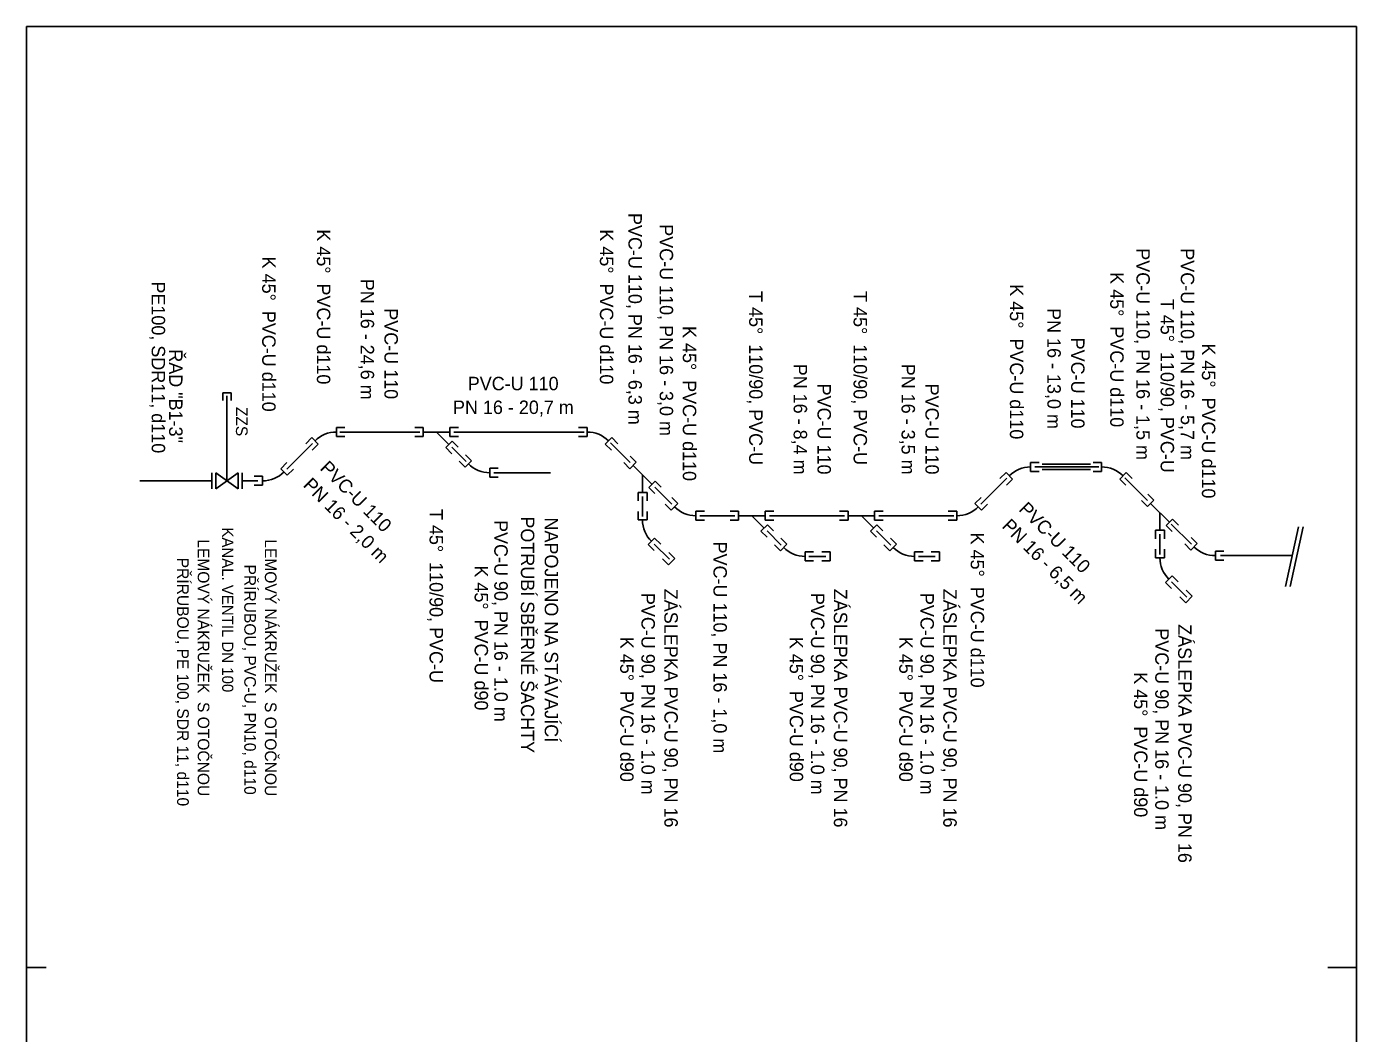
# Model space of a CAD drawing. Extents: x -549136 to -548786, y -1151900 to -1151213.
# Drawn here: x -549136 to -548987.5, y -1151446.3 to -1151333.9 of the extents above; entities that cross this region are included whole.
import ezdxf

# ---------------------------------------------------------------- set-up
doc = ezdxf.new("R2010")
doc.units = 0
doc.layers.add('Vrstva 2', color=7, linetype='Continuous')

msp = doc.modelspace()

# ---------------------------------------------------------------- linework, layer by layer
at = {"layer": 'Vrstva 2'}
for p, q in [((-548987.55, -1151333.9), (-549136.05, -1151333.9)), ((-549136.05, -1151333.9), (-549136.05, -1151438.9)), ((-548987.55, -1151438.9), (-548987.55, -1151333.9)), ((-549114.14, -1151374.78), (-549113.19, -1151374.78)), ((-549114.14, -1151374.78), (-549114.14, -1151375.64)), ((-549113.67, -1151384.6), (-549113.67, -1151375.12)), ((-549113.19, -1151374.78), (-549113.19, -1151375.64)), ((-549104.19, -1151379.78), (-549104.87, -1151380.46)), ((-549104.19, -1151379.78), (-549103.48, -1151380.5)), ((-549101.45, -1151379.66), (-549101.45, -1151378.65)), ((-549101.45, -1151378.65), (-549100.5, -1151378.65)), ((-549101.45, -1151379.66), (-549100.5, -1151379.66)), ((-549101.06, -1151379.15), (-549092.14, -1151379.15)), ((-549091.75, -1151378.65), (-549092.7, -1151378.65)), ((-549091.75, -1151379.66), (-549092.7, -1151379.66)), ((-549091.75, -1151378.65), (-549091.75, -1151379.66)), ((-549091.75, -1151379.15), (-549088.78, -1151379.15)), ((-549090.26, -1151379.15), (-549088.88, -1151380.53)), ((-549088.78, -1151378.65), (-549088.78, -1151379.66)), ((-549088.78, -1151378.65), (-549087.83, -1151378.65)), ((-549088.78, -1151379.66), (-549087.83, -1151379.66)), ((-549088.33, -1151379.15), (-549073.77, -1151379.15)), ((-549073.45, -1151378.65), (-549074.4, -1151378.65)), ((-549073.45, -1151379.66), (-549074.4, -1151379.66)), ((-549073.45, -1151378.65), (-549073.45, -1151379.66)), ((-549071.42, -1151380.5), (-549070.7, -1151379.78)), ((-549070.7, -1151379.78), (-549070.03, -1151380.46)), ((-549107, -1151383.31), (-549104.12, -1151380.43)), ((-549103.48, -1151380.5), (-549104.15, -1151381.18)), ((-549088.52, -1151380.17), (-549089.24, -1151380.89)), ((-549089.24, -1151380.89), (-549088.57, -1151381.57)), ((-549088.57, -1151380.85), (-549086.97, -1151382.45)), ((-549088.52, -1151380.17), (-549087.85, -1151380.85)), ((-549071.42, -1151380.5), (-549070.74, -1151381.18)), ((-549070.85, -1151380.35), (-549068.65, -1151382.55)), ((-549107.66, -1151383.25), (-549106.98, -1151382.57)), ((-549087.07, -1151383.07), (-549087.74, -1151382.39)), ((-549086.35, -1151382.35), (-549087.07, -1151383.07)), ((-549086.35, -1151382.35), (-549087.02, -1151381.68)), ((-549068.68, -1151383.25), (-549069.35, -1151382.57)), ((-549067.96, -1151382.53), (-549068.68, -1151383.25)), ((-549067.96, -1151382.53), (-549068.63, -1151381.85)), ((-549023.93, -1151383.56), (-549023.93, -1151382.54)), ((-549023.93, -1151382.54), (-549022.97, -1151382.54)), ((-549022.65, -1151382.75), (-549017.24, -1151382.75)), ((-549016, -1151382.54), (-549016.95, -1151382.54)), ((-549016, -1151382.54), (-549016, -1151383.56)), ((-549115.35, -1151385.5), (-549115.35, -1151383.7)), ((-549114.92, -1151385.5), (-549114.92, -1151383.7)), ((-549114.92, -1151383.7), (-549112.42, -1151385.5)), ((-549112.42, -1151383.7), (-549114.92, -1151385.5)), ((-549112.42, -1151385.5), (-549112.42, -1151383.7)), ((-549111.98, -1151385.5), (-549111.98, -1151383.7)), ((-549109.69, -1151384.09), (-549110.64, -1151384.09)), ((-549109.69, -1151384.09), (-549109.69, -1151385.1)), ((-549106.94, -1151383.97), (-549107.66, -1151383.25)), ((-549106.94, -1151383.97), (-549106.26, -1151383.29)), ((-549084.32, -1151384.2), (-549084.32, -1151383.19)), ((-549084.32, -1151383.19), (-549083.37, -1151383.19)), ((-549084.32, -1151384.2), (-549083.37, -1151384.2)), ((-549083.88, -1151383.7), (-549077.56, -1151383.7)), ((-549068.32, -1151382.89), (-549066.22, -1151384.98)), ((-549067.27, -1151383.94), (-549067.27, -1151385.89)), ((-549029.48, -1151387.21), (-549026.6, -1151384.32)), ((-549026.67, -1151383.68), (-549027.35, -1151384.35)), ((-549026.67, -1151383.68), (-549025.95, -1151384.4)), ((-549023.93, -1151383.56), (-549022.97, -1151383.56)), ((-549023.47, -1151383.05), (-549016.32, -1151383.05)), ((-549022.65, -1151383.35), (-549017.24, -1151383.35)), ((-549016, -1151383.56), (-549016.95, -1151383.56)), ((-549013.97, -1151384.4), (-549013.25, -1151383.68)), ((-549013.4, -1151384.25), (-549010.87, -1151386.78)), ((-549013.25, -1151383.68), (-549012.58, -1151384.35)), ((-549117.11, -1151384.6), (-549123.41, -1151384.6)), ((-549115.35, -1151384.6), (-549117.11, -1151384.6)), ((-549110.22, -1151384.6), (-549111.98, -1151384.6)), ((-549109.69, -1151385.1), (-549110.64, -1151385.1)), ((-549065.86, -1151384.63), (-549066.58, -1151385.34)), ((-549066.58, -1151385.34), (-549065.9, -1151386.02)), ((-549065.9, -1151385.31), (-549063.99, -1151387.21)), ((-549065.86, -1151384.63), (-549065.18, -1151385.3)), ((-549025.95, -1151384.4), (-549026.63, -1151385.07)), ((-549013.97, -1151384.4), (-549013.3, -1151385.07)), ((-549066.76, -1151385.89), (-549067.77, -1151385.89)), ((-549067.77, -1151385.89), (-549067.77, -1151386.84)), ((-549067.27, -1151386.33), (-549067.27, -1151388.59)), ((-549066.76, -1151385.89), (-549066.76, -1151386.84)), ((-549064.06, -1151387.86), (-549064.73, -1151387.19)), ((-549063.34, -1151387.14), (-549064.06, -1151387.86)), ((-549063.34, -1151387.14), (-549064.01, -1151386.47)), ((-549030.14, -1151387.14), (-549029.46, -1151386.47)), ((-549029.42, -1151387.86), (-549030.14, -1151387.14)), ((-549029.42, -1151387.86), (-549028.74, -1151387.19)), ((-549010.89, -1151387.48), (-549011.56, -1151386.8)), ((-549010.17, -1151386.76), (-549010.89, -1151387.48)), ((-549010.17, -1151386.76), (-549010.84, -1151386.08)), ((-549010.53, -1151387.12), (-549008.43, -1151389.22)), ((-549067.77, -1151388.96), (-549067.77, -1151388.01)), ((-549066.76, -1151388.96), (-549066.76, -1151388.01)), ((-549061.31, -1151389), (-549061.31, -1151387.98)), ((-549061.31, -1151387.98), (-549060.36, -1151387.98)), ((-549060.87, -1151388.49), (-549056.94, -1151388.49)), ((-549056.54, -1151387.98), (-549057.49, -1151387.98)), ((-549056.54, -1151387.98), (-549056.54, -1151389)), ((-549056.54, -1151388.49), (-549053.57, -1151388.49)), ((-549055.06, -1151388.49), (-549053.68, -1151389.87)), ((-549053.57, -1151387.98), (-549053.57, -1151389)), ((-549053.57, -1151387.98), (-549052.62, -1151387.98)), ((-549053.1, -1151388.49), (-549044.71, -1151388.49)), ((-549044.31, -1151387.98), (-549045.27, -1151387.98)), ((-549044.31, -1151387.98), (-549044.31, -1151389)), ((-549044.31, -1151388.49), (-549041.35, -1151388.49)), ((-549042.83, -1151388.49), (-549041.45, -1151389.87)), ((-549041.35, -1151387.98), (-549041.35, -1151389)), ((-549041.35, -1151387.98), (-549040.4, -1151387.98)), ((-549040.88, -1151388.49), (-549032.49, -1151388.49)), ((-549032.16, -1151387.98), (-549033.12, -1151387.98)), ((-549032.16, -1151387.98), (-549032.16, -1151389)), ((-549009.48, -1151388.17), (-549009.48, -1151390.12)), ((-549066.76, -1151388.96), (-549067.77, -1151388.96)), ((-549061.31, -1151389), (-549060.36, -1151389)), ((-549056.54, -1151389), (-549057.49, -1151389)), ((-549053.32, -1151389.51), (-549054.04, -1151390.23)), ((-549054.04, -1151390.23), (-549053.36, -1151390.9)), ((-549053.57, -1151389), (-549052.62, -1151389)), ((-549053.36, -1151390.18), (-549051.77, -1151391.78)), ((-549053.32, -1151389.51), (-549052.65, -1151390.18)), ((-549044.31, -1151389), (-549045.27, -1151389)), ((-549041.09, -1151389.51), (-549041.81, -1151390.23)), ((-549041.81, -1151390.23), (-549041.14, -1151390.9)), ((-549041.35, -1151389), (-549040.4, -1151389)), ((-549041.14, -1151390.18), (-549039.54, -1151391.78)), ((-549041.09, -1151389.51), (-549040.42, -1151390.18)), ((-549032.16, -1151389), (-549033.12, -1151389)), ((-549008.97, -1151390.12), (-549009.99, -1151390.12)), ((-549009.99, -1151390.12), (-549009.99, -1151391.07)), ((-549008.97, -1151390.12), (-549008.97, -1151391.07)), ((-549008.07, -1151388.86), (-549008.79, -1151389.58)), ((-549008.79, -1151389.58), (-549008.12, -1151390.25)), ((-549008.22, -1151389.43), (-549005.98, -1151391.66)), ((-549008.07, -1151388.86), (-549007.4, -1151389.53)), ((-548994, -1151389.73), (-548995.46, -1151396.4)), ((-548993.48, -1151389.73), (-548994.94, -1151396.4)), ((-549066.64, -1151391.71), (-549065.92, -1151390.99)), ((-549066.64, -1151391.71), (-549065.96, -1151392.38)), ((-549065.97, -1151391.66), (-549064.27, -1151393.35)), ((-549065.92, -1151390.99), (-549065.24, -1151391.66)), ((-549051.86, -1151392.4), (-549052.54, -1151391.73)), ((-549051.14, -1151391.68), (-549051.86, -1151392.4)), ((-549051.14, -1151391.68), (-549051.82, -1151391.01)), ((-549039.64, -1151392.4), (-549040.31, -1151391.73)), ((-549038.92, -1151391.68), (-549039.64, -1151392.4)), ((-549038.92, -1151391.68), (-549039.59, -1151391.01)), ((-549009.48, -1151390.56), (-549009.48, -1151392.82)), ((-549006.05, -1151392.32), (-549006.72, -1151391.64)), ((-549005.33, -1151391.6), (-549006.05, -1151392.32)), ((-549005.33, -1151391.6), (-549006, -1151390.93)), ((-549064.38, -1151393.97), (-549063.66, -1151393.25)), ((-549063.66, -1151393.25), (-549064.33, -1151392.58)), ((-549049.11, -1151393.54), (-549049.11, -1151392.52)), ((-549049.11, -1151392.52), (-549048.16, -1151392.52)), ((-549048.68, -1151393.03), (-549046.81, -1151393.03)), ((-549046.31, -1151392.52), (-549047.26, -1151392.52)), ((-549046.31, -1151392.52), (-549046.31, -1151393.54)), ((-549036.89, -1151393.54), (-549036.89, -1151392.52)), ((-549036.89, -1151392.52), (-549035.94, -1151392.52)), ((-549036.45, -1151393.03), (-549034.58, -1151393.03)), ((-549034.09, -1151392.52), (-549035.04, -1151392.52)), ((-549034.09, -1151392.52), (-549034.09, -1151393.54)), ((-549009.99, -1151393.19), (-549009.99, -1151392.24)), ((-549008.97, -1151393.19), (-549009.99, -1151393.19)), ((-549008.97, -1151393.19), (-549008.97, -1151392.24)), ((-549003.3, -1151393.46), (-549003.3, -1151392.44)), ((-549003.3, -1151392.44), (-549002.35, -1151392.44)), ((-549002.73, -1151392.95), (-548994.7, -1151392.95)), ((-549064.38, -1151393.97), (-549065.05, -1151393.3)), ((-549049.11, -1151393.54), (-549048.16, -1151393.54)), ((-549046.31, -1151393.54), (-549047.26, -1151393.54)), ((-549036.89, -1151393.54), (-549035.94, -1151393.54)), ((-549034.09, -1151393.54), (-549035.04, -1151393.54)), ((-549003.3, -1151393.46), (-549002.35, -1151393.46)), ((-549008.85, -1151395.94), (-549008.13, -1151395.22)), ((-549008.85, -1151395.94), (-549008.18, -1151396.61)), ((-549008.18, -1151395.89), (-549006.49, -1151397.58)), ((-549008.13, -1151395.22), (-549007.46, -1151395.89)), ((-549006.59, -1151398.2), (-549007.26, -1151397.53)), ((-549006.59, -1151398.2), (-549005.87, -1151397.48)), ((-549005.87, -1151397.48), (-549006.54, -1151396.81)), ((-549136.05, -1151438.9), (-549136.05, -1151543.9)), ((-549133.86, -1151438.9), (-549136.05, -1151438.9)), ((-548987.55, -1151438.9), (-548990.75, -1151438.9)), ((-548987.55, -1151543.9), (-548987.55, -1151438.9))]:
    msp.add_line(p, q, dxfattribs=at)
for centre, start, end in [((-549101.45, -1151382.53), 90, 135), ((-549073.45, -1151382.53), 45, 90), ((-549084.32, -1151380.32), 225, 270), ((-549109.69, -1151381.22), 270, 315), ((-549023.93, -1151386.43), 90, 135), ((-549016, -1151386.43), 45, 90), ((-549061.31, -1151385.11), 225, 270), ((-549032.16, -1151385.11), 270, 315), ((-549063.89, -1151388.96), 180, 225), ((-549049.11, -1151389.65), 225, 270), ((-549036.89, -1151389.65), 225, 270), ((-549006.1, -1151393.19), 180, 225), ((-549003.3, -1151389.57), 225, 270)]:
    msp.add_arc(centre, 3.38, start, end, dxfattribs=at)

# ---------------------------------------------------------------- texts
for s, height, rotation, p in [(' PVC-U 110, PN 16 - 6,3 m', 1.5, 270, (-549068.84, -1151354.15)), (' PVC-U 110, PN 16 - 3,0 m', 1.5, 270, (-549065.35, -1151355.4)), ('K 45°  PVC-U d110', 1.5, 270, (-549103.63, -1151356.53)), ('K 45°  PVC-U d110', 1.5, 270, (-549072.03, -1151356.53)), (' PVC-U 110, PN 16 - 1,5 m', 1.5, 270, (-549012.12, -1151358.08)), (' PVC-U 110, PN 16 - 5,7 m', 1.5, 270, (-549007.16, -1151358.08)), ('K 45°  PVC-U d110', 1.5, 270, (-549109.74, -1151359.58)), ('K 45°  PVC-U d110', 1.5, 270, (-549015.04, -1151361.31)), ('PE100, SDR11, d110', 1.5, 270, (-549122.08, -1151362.34)), (' PN 16 - 24,6 m', 1.5, 270, (-549098.74, -1151361.49)), ('T 45°  110/90, PVC-U ', 1.5, 270, (-549055.36, -1151363.42)), ('T 45°  110/90, PVC-U ', 1.5, 270, (-549043.7, -1151363.42)), ('K 45°  PVC-U d110', 1.5, 270, (-549026.24, -1151362.66)), ('T 45°  110/90, PVC-U ', 1.5, 270, (-549009.41, -1151364.28)), (' PVC-U 110', 1.5, 270, (-549096.09, -1151364.78)), (' PN 16 - 13,0 m', 1.5, 270, (-549022.06, -1151364.76)), ('K 45°  PVC-U d110', 1.5, 270, (-549062.77, -1151367.32)), (' PVC-U 110', 1.5, 270, (-549019.41, -1151368.06)), ('K 45°  PVC-U d110', 1.5, 270, (-549004.8, -1151369.26)), ('ŘAD "B1-3"', 1.5, 270, (-549120.13, -1151369.92)), (' PN 16 - 8,4 m', 1.5, 270, (-549050.39, -1151370.97)), (' PN 16 - 3,5 m', 1.5, 270, (-549038.34, -1151370.97)), (' PVC-U 110', 1.5, 270, (-549047.73, -1151373.19)), (' PVC-U 110', 1.5, 270, (-549035.68, -1151373.19)), ('ZZS', 1.3, 270, (-549112.67, -1151376.34)), (' PVC-U 110', 1.5, 315, (-549103.77, -1151382.89)), (' PN 16 - 2,0 m', 1.5, 315, (-549105.65, -1151384.77)), (' PVC-U 110', 1.5, 315, (-549025.74, -1151387.47)), ('T 45°  110/90, PVC-U ', 1.5, 270, (-549091.05, -1151387.74)), (' POTRUBÍ SBĚRNÉ ŠACHTY', 1.5, 270, (-549080.85, -1151388.01)), (' PN 16 - 6,5 m', 1.5, 315, (-549027.62, -1151389.34)), ('KANAL. VENTIL DN 100', 1.25, 270, (-549114.21, -1151389.8)), (' PVC-U 90, PN 16 - 1.0 m', 1.5, 270, (-549083.82, -1151388.42)), ('NAPOJENO NA STÁVAJÍCÍ ', 1.5, 270, (-549078.19, -1151388.69)), ('LEMOVÝ NÁKRUŽEK  S OTOČNOU ', 1.3, 270, (-549116.94, -1151391.12)), ('LEMOVÝ NÁKRUŽEK  S OTOČNOU ', 1.3, 270, (-549109.44, -1151391.12)), (' PVC-U 110, PN 16 - 1,0 m', 1.5, 270, (-549059.35, -1151390.82)), ('K 45°  PVC-U d110', 1.5, 270, (-549030.62, -1151390.38)), ('PŘÍRUBOU, PE 100, SDR 11, d110', 1.3, 270, (-549119.24, -1151393.18)), ('PŘÍRUBOU, PVC-U, PN10, d110', 1.3, 270, (-549111.74, -1151393.94)), ('K 45°  PVC-U d90', 1.5, 270, (-549086.02, -1151394.04)), (' PVC-U 90, PN 16 - 1.0 m', 1.5, 270, (-549067.39, -1151396.55)), (' ZÁSLEPKA PVC-U 90, PN 16 ', 1.5, 270, (-549064.83, -1151396.09)), (' PVC-U 90, PN 16 - 1.0 m', 1.5, 270, (-549048.46, -1151396.55)), (' ZÁSLEPKA PVC-U 90, PN 16 ', 1.5, 270, (-549045.9, -1151396.09)), (' PVC-U 90, PN 16 - 1.0 m', 1.5, 270, (-549036.23, -1151396.55)), (' ZÁSLEPKA PVC-U 90, PN 16 ', 1.5, 270, (-549033.68, -1151396.09)), (' ZÁSLEPKA PVC-U 90, PN 16 ', 1.5, 270, (-549007.45, -1151400.04)), (' PVC-U 90, PN 16 - 1.0 m', 1.5, 270, (-549010.01, -1151400.5)), ('K 45°  PVC-U d90', 1.5, 270, (-549069.76, -1151402.01)), ('K 45°  PVC-U d90', 1.5, 270, (-549050.83, -1151402.01)), ('K 45°  PVC-U d90', 1.5, 270, (-549038.6, -1151402.01)), ('K 45°  PVC-U d90', 1.5, 270, (-549012.38, -1151405.96))]:
    msp.add_text(s, height=height, rotation=rotation, dxfattribs=at).set_placement(p)
for s, p in [(' PVC-U 110', (-549087.34, -1151374.49)), (' PN 16 - 20,7 m', (-549088.99, -1151377.14))]:
    msp.add_text(s, height=1.5, dxfattribs=at).set_placement(p)

doc.saveas('drawing.dxf')
